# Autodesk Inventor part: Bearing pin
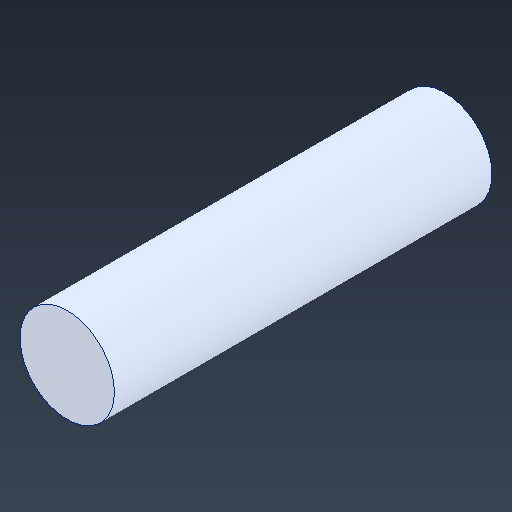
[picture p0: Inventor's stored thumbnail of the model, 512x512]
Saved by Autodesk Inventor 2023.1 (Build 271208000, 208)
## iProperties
Created: 2020-02
Part Number: Bearing pin
Material: SOLIDWORKS Materials|6061 Alloy
Document SubType Name: Modeling
Designer: ftrauzettel
Density: 2.7 g/cm^3
Appearance: 221,232,255
Sending System: SolidWorks 2016
Last Author: Pam
Last Saved: 2020-02-20
Author: ftrauzettel
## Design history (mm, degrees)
feature "Boss-Extrude1"
body "Solid1"
